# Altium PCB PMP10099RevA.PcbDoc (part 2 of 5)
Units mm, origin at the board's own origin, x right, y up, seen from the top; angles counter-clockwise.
Board outline 227.58 x 89.92 mm, 2 copper layers (Top Layer, Bottom Layer), stack 1.575 mm thick; 558 components, 261 nets, 1374 pads, 560 vias.
Unrouted connection lines stored in the file: 7.
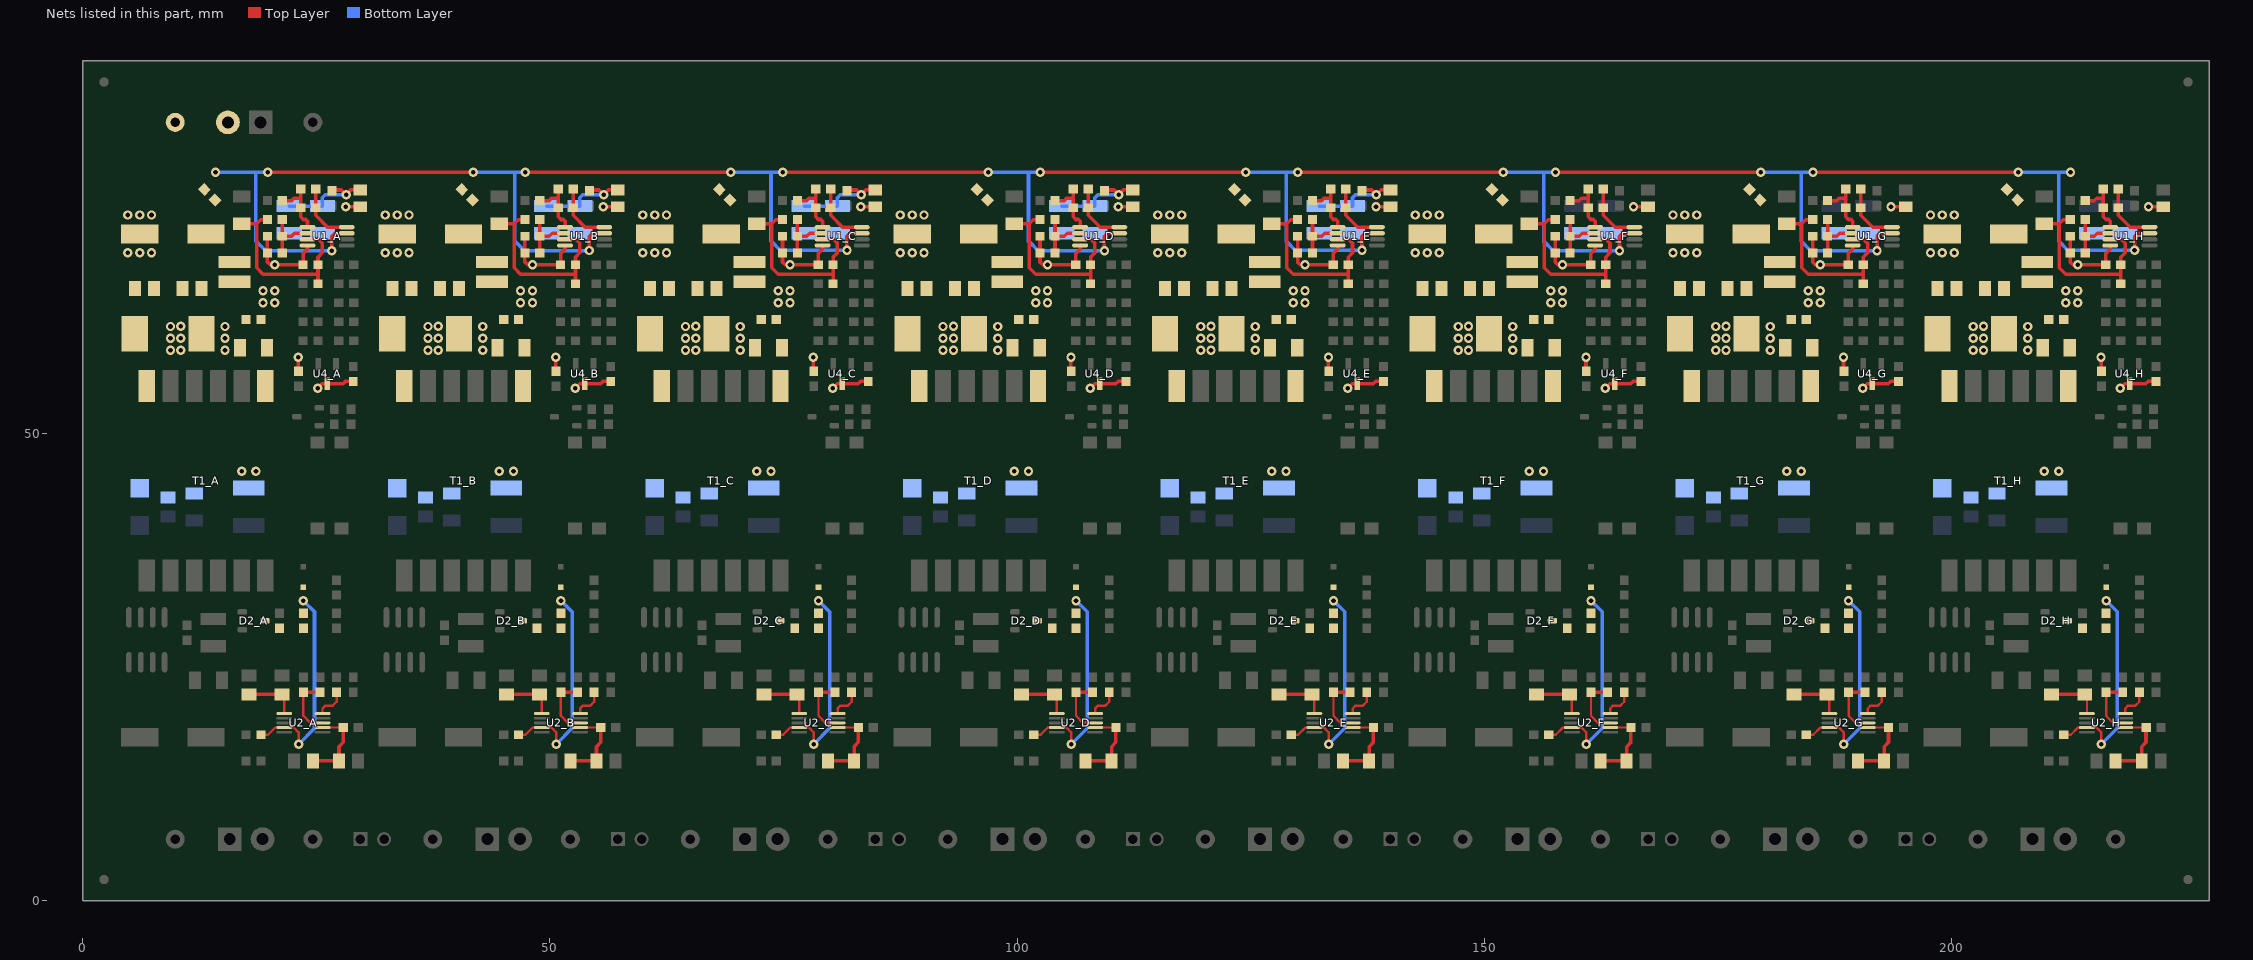
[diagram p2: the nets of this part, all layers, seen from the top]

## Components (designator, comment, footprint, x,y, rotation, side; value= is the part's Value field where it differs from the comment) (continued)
U1_H "UCC29002" DGK0008A_N 219.075,71.12 r0 top (schematic designator U1)
U2_A "LM5022" MUB10A_N 23.622,19.05 r0 top (schematic designator U2)
U2_B "LM5022" MUB10A_N 51.181,19.05 r0 top (schematic designator U2)
U2_C "LM5022" MUB10A_N 78.74,19.05 r0 top (schematic designator U2)
U2_D "LM5022" MUB10A_N 106.299,19.05 r0 top (schematic designator U2)
U2_E "LM5022" MUB10A_N 133.858,19.05 r0 top (schematic designator U2)
U2_F "LM5022" MUB10A_N 161.417,19.05 r0 top (schematic designator U2)
U2_G "LM5022" MUB10A_N 188.976,19.05 r0 top (schematic designator U2)
U2_H "LM5022" MUB10A_N 216.535,19.05 r0 top (schematic designator U2)
U3_A "FOD817A" N04C 26.416,44.45 r270 top (schematic designator U3)
U3_B "FOD817A" N04C 53.975,44.45 r270 top (schematic designator U3)
U3_C "FOD817A" N04C 81.534,44.45 r270 top (schematic designator U3)
U3_D "FOD817A" N04C 109.093,44.45 r270 top (schematic designator U3)
U3_E "FOD817A" N04C 136.652,44.45 r270 top (schematic designator U3)
U3_F "FOD817A" N04C 164.211,44.45 r270 top (schematic designator U3)
U3_G "FOD817A" N04C 191.77,44.45 r270 top (schematic designator U3)
U3_H "FOD817A" N04C 219.329,44.45 r270 top (schematic designator U3)
U4_A "LMV431" MF03A_N 26.162,56.388 r270 top (schematic designator U4)
U4_B "LMV431" MF03A_N 53.721,56.388 r270 top (schematic designator U4)
U4_C "LMV431" MF03A_N 81.28,56.388 r270 top (schematic designator U4)
U4_D "LMV431" MF03A_N 108.839,56.388 r270 top (schematic designator U4)
U4_E "LMV431" MF03A_N 136.398,56.388 r270 top (schematic designator U4)
U4_F "LMV431" MF03A_N 163.957,56.388 r270 top (schematic designator U4)
U4_G "LMV431" MF03A_N 191.516,56.388 r270 top (schematic designator U4)
U4_H "LMV431" MF03A_N 219.075,56.388 r270 top (schematic designator U4)

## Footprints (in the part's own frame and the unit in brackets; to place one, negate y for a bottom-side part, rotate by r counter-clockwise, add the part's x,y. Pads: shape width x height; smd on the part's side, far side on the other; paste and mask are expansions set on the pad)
0603 [mm] "0603 from SM-752 data"
  rect 1x0.95 smd: 1(-0.8,0) 2(0.8,0)
  silkscreen extent -1.52,-0.69 1.52,0.69, body extent -0.87,-0.47 0.87,0.47, height 0.85
0805_140 [mm] "0805 / 1.4mm height"
  rect 1.15x1.45 smd: 1(-0.9,0) 2(0.9,0)
  silkscreen extent -0.1,-0.8 0.1,0.8, body extent -1.1,-0.72 1.1,0.72, height 1.4
0805_HV [mil] "0805 with 30mil clearance between pads"
  rect 50x63 smd: 1(-40,0) 2(40,0)
  silkscreen extent -74,-40 74,40, body extent -43,-29 43,29, height 43
1206 [mm] "1206 from SM-752 data"
  rect 1.3x1.85 smd: 1(-1.45,0) 2(1.45,0)
  silkscreen extent -2.4,-1.21 2.4,1.21, body extent -1.7,-0.9 1.7,0.9, height 1.35
1210 [mm] "1210 from SM-752 data"
  rect 1.3x2.7 smd: 1(-1.45,0) 2(1.45,0)
  silkscreen extent -2.32,-1.57 2.32,1.57, body extent -1.7,-1.35 1.7,1.35, height 1.35
1812 [mm]
  rect 1.6x3.4 smd: 1(-2,0) 2(2,0)
  silkscreen extent -0.8,-1.6 0.8,1.6, body extent -2.4,-1.7 2.4,1.7, height 1.35
CONN_PEC02SAAN [mm] "SULLINS"
  rect 1.5x1.5 hole 1.016: 1(-1.27,0)
  round 1.5 hole 1.016: 2(1.27,0)
  silkscreen extent -2.54,-1.27 2.54,1.27, body extent -2.54,-1.27 2.54,1.27, height 8.38
DGK0008A_N [mm] "TSOP, 8-Leads, Body 3x3mm, Pitch 0.65mm, IPC Medium Density"
  oval 1.7x0.45 smd mask+0.05: 1(-2.1,0.975) 2(-2.1,0.325) 3(-2.1,-0.325) 4(-2.1,-0.975) 5(2.1,-0.975) 6(2.1,-0.325) 7(2.1,0.325) 8(2.1,0.975)
  silkscreen extent -0.95,-1.55 0.95,1.55, body extent -2.45,-1.5 2.45,1.5, height 0.94
Fiducial10-30 [mm]
  round 1 smd mask+1: 1(0,0)
  Top Layer keep-out circle w1.678: c0,0 r0.75
Keystone5000 [mil] "For Keystone 500x miniature loop terminals"
  round 80 hole 40: 1(0,0)
  silkscreen extent -58,-58 58,58, body extent -49,-49 49,49, height 182
Keystone5001 [mil] "For Keystone 500x miniature loop terminals"
  round 80 hole 40: 1(0,0)
  silkscreen extent -58,-58 58,58, body extent -49,-49 49,49, height 182
MF03A_N [mm] "SOT23, 3-Leads, Body 2.9x1.3mm, Pitch 0.95mm, Lead Span 2.4mm, IPC Medium Density"
  rect 1.3x0.6 smd: 1(-1.05,0.95) 2(-1.05,-0.95) 3(1.05,0)
  silkscreen extent -1.17,-1.5 0.7,1.93, body extent -0.7,-1.5 0.7,1.5, height 1.12
MUB10A_N [mm] "TSSOP, 10-Leads, Body 3x3mm, Pitch 0.5mm, IPC Medium Density"
  oval 1.7x0.3 smd: 1(-2.05,1) 2(-2.05,0.5) 3(-2.05,0) 4(-2.05,-0.5) 5(-2.05,-1) 6(2.05,-1) 7(2.05,-0.5) 8(2.05,0) 9(2.05,0.5) 10(2.05,1)
  silkscreen extent -2.17,-1.6 0.8,1.82, body extent -1.6,-1.6 1.6,1.6, height 1.09
N04C [mm] "FAIRCHILD"
  rect 1.3x1.5 smd mask+0.065: 1(-4.587,1.27) 2(-4.612,-1.27) 3(4.588,-1.27) 4(4.613,1.27)
  silkscreen extent -3.56,-2.3 3.56,2.72, body extent -5.08,-2.3 5.08,2.3, height 3.87
SM_RADIAL_F [mm] "8 x 10.2mm:  Panasonic F"
  rect 4x2 smd: 1(-3.55,0) 2(3.55,0)
  silkscreen extent -4.25,-4.25 4.25,4.25, body extent -4.26,-4.26 4.26,4.26, height 10.5
SMA [mm] "Molded Diode, 2-Leads, Body 4.3x2.6mm, IPC Medium Density, based on OnSemi component dimensions and land pattern"
  rect 2x2 smd: 1(-2,0) 2(2,0)
  silkscreen extent -3.66,-1.57 2.79,1.57, body extent -2.6,-1.3 2.6,1.3, height 2.42
SMC [mil] "Molded Diode, 2-Leads, Body 6.9x5.8mm, IPC Medium Density, based on OnSemi component dimensions and land patterns"
  rect 110x150 smd: 1(-140.49,0) 2(140.49,0)
  silkscreen extent -221,-123 189,124, body extent -156,-116 156,116, height 91
sod-323 [mm] "NXP recommended land pattern"
  rect 0.6x0.6 smd paste-0.05: 1(-1.1,0) 2(1.1,0)
  silkscreen extent -2.06,-0.86 1.53,0.86, body extent -1.3,-0.67 1.3,0.68, height 1.1
SOIC-8 [mm] "duplicate of SO-8.  SOIC, 8-Leads, Body 5.0x4.0mm (max), Pitch 1.27mm, IPC Medium Density"
  oval 2.2x0.6 smd: 1(-2.4,1.905) 2(-2.4,0.635) 3(-2.4,-0.635) 4(-2.4,-1.905) 5(2.4,-1.905) 6(2.4,-0.635) 7(2.4,0.635) 8(2.4,1.905)
  silkscreen extent -0.9,-2.5 0.9,2.5, body extent -3,-2.45 3,2.45, height 1.63
SOT-23 [mm] "SOT23, 3-Leads, Body 2.9x1.3mm, Pitch 0.95mm, Lead Span 2.5mm, IPC Medium Density"
  rrect50% 1x0.6 smd: 1(-1.2,0.95) 2(-1.2,-0.95) 3(1.2,0)
  silkscreen extent -1.63,-1.5 0.7,1.5, body extent -1.16,-1.45 1.21,1.45, height 1
TERM_BLK_ED555-2DS [mil]
  rect 100x100 hole 50: 1(0,0)
  round 100 hole 50: 2(138,0)
  silkscreen extent -77,-159 215,113, body extent -69,-150 207,106, height 323
WE-MAPI_3020 [mm] "SMD, 2-Leads, Body 3.2x3.2mm"
  rect 1.3x3.4 smd: 1(-1.05,0) 2(1.05,0)
  silkscreen extent -0.1,-1.6 0.1,1.6, body extent -1.6,-1.6 1.6,1.6, height 2
WURTH_7491193912 [mm] "SMT, 12-Leads, Body 17.5x16mm, Pitch 2.54mm"
  rect 3.43x1.75 smd: 1(-10.155,6.35) 2(-10.155,3.81) 3(-10.155,1.27) 4(-10.155,-1.27) 5(-10.155,-3.81) 6(-10.155,-6.35) 7(10.155,-6.35) 8(10.155,-3.81) 9(10.155,-1.27) 10(10.155,1.27) 11(10.155,3.81) 12(10.155,6.35)
  silkscreen extent -8.5,-8.75 8,8.85, body extent -11.05,-8.75 11.05,8.75, height 8.3

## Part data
C1_A C1_B C1_C C1_D C1_E C1_F C1_G C1_H: "CAP, AL, 22 µF, 80 V, +/- 20%, 1.3 ohm, SMD"
C2_A C2_B C2_C C2_D C2_E C2_F C2_G C2_H: "CAP, CERM, 2.2 µF, 100 V, +/- 10%, X7R, 1210"
C3_A C3_B C3_C C3_D C3_E C3_F C3_G C3_H C8_A C8_B C8_C C8_D C8_E C8_F C8_G C8_H C9_A C9_B C9_C C9_D C9_E C9_F C9_G C9_H C14_A C14_B C14_C C14_D C14_E C14_F C14_G C14_H C16_A C16_B C16_C C16_D C16_E C16_F C16_G C16_H C24_A C24_B C24_C C24_D C24_E C24_F C24_G C24_H: "CAP, CERM, 0.1 µF, 50 V, +/- 10%, X7R, 0603"
C4_A C4_B C4_C C4_D C4_E C4_F C4_G C4_H C10_A C10_B C10_C C10_D C10_E C10_F C10_G C10_H: "CAP, CERM, 0.1 µF, 100 V, +/- 10%, X7R, 0805"
C5_A C5_B C5_C C5_D C5_E C5_F C5_G C5_H: "CAP, CERM, 33 pF, 100 V, +/- 5%, C0G/NP0, 0805"
C6_A C6_B C6_C C6_D C6_E C6_F C6_G C6_H: "CAP, AL, 330 µF, 16 V, +/- 20%, 0.16 ohm, SMD"
C7_A C7_B C7_C C7_D C7_E C7_F C7_G C7_H: "CAP, CERM, 10 µF, 25 V, +/- 10%, X7R, 1206"
C11_A C11_B C11_C C11_D C11_E C11_F C11_G C11_H C17_A C17_B C17_C C17_D C17_E C17_F C17_G C17_H C26_A C26_B C26_C C26_D C26_E C26_F C26_G C26_H: "CAP, CERM, 1 µF, 25 V, +/- 10%, X7R, 0603"
C12_A C12_B C12_C C12_D C12_E C12_F C12_G C12_H C13_A C13_B C13_C C13_D C13_E C13_F C13_G C13_H: "CAP, CERM, 56 pF, 50 V, +/- 5%, C0G/NP0, 0603"
C15_A C15_B C15_C C15_D C15_E C15_F C15_G C15_H C18_A C18_B C18_C C18_D C18_E C18_F C18_G C18_H: "CAP, CERM, 1000 pF, 50 V, +/- 10%, X7R, 0603"
C19_A C19_B C19_C C19_D C19_E C19_F C19_G C19_H C20_A C20_B C20_C C20_D C20_E C20_F C20_G C20_H: "CAP, CERM, 47 µF, 6.3 V, +/- 10%, X7R, 1210"
C21_A C21_B C21_C C21_D C21_E C21_F C21_G C21_H: "CAP, CERM, 10 µF, 10 V, +/- 10%, X7R, 0805_140"
C22_A C22_B C22_C C22_D C22_E C22_F C22_G C22_H: "CAP, CERM, 22 pF, 50 V, +/- 5%, C0G/NP0, 0603"
C23_A C23_B C23_C C23_D C23_E C23_F C23_G C23_H: "CAP, CERM, 4700 pF, 50 V, +/- 10%, X7R, 0603"
C25_A C25_B C25_C C25_D C25_E C25_F C25_G C25_H: "CAP, CERM, 1000 pF, 2000 V, +/- 10%, X7R, 1812"
D1_A D1_B D1_C D1_D D1_E D1_F D1_G D1_H: library part MURA120T3G, "Diode, Ultrafast, 200 V, 1 A, SMA"
D2_A D2_B D2_C D2_D D2_E D2_F D2_G D2_H D5_A D5_B D5_C D5_D D5_E D5_F D5_G D5_H: library part BAS16-7-F, "Diode, Ultrafast, 75 V, 0.3 A, SOT-23"
D3_A D3_B D3_C D3_D D3_E D3_F D3_G D3_H: library part MBRS340T3G, "Diode, Schottky, 60 V, 3 A, SMC"
D4_A D4_B D4_C D4_D D4_E D4_F D4_G D4_H: "Diode, Zener, 12 V, 300 mW, SOD-323"
FID1 FID2 FID3 FID4: "Fiducial mark.  There is nothing to buy or mount."
J1_A J1_B J1_C J1_D J1_E J1_F J1_G J1_H J9: "Terminal Block, 6A, 3.5mm Pitch, 2-Pos, TH"
J2 J3 J4 J5 J6 J7 J8: "Header, 100mil, 2x1, Tin, TH"
L1_A L1_B L1_C L1_D L1_E L1_F L1_G L1_H: library part 744383360033, "Inductor, 330 nH, 5.5 A, 0.014 ohm, SMD"
Q1_A Q1_B Q1_C Q1_D Q1_E Q1_F Q1_G Q1_H: "MOSFET, N-CH, 150 V, 4.1 A, SOIC-8"
R1_A R1_B R1_C R1_D R1_E R1_F R1_G R1_H: "RES, 47 k, 5%, 0.25 W, 1206"
R2_A R2_B R2_C R2_D R2_E R2_F R2_G R2_H: "RES, 100 ohm, 5%, 0.125W, 0805"
R3_A R3_B R3_C R3_D R3_E R3_F R3_G R3_H: "RES, 0.1, 5%, 0.25 W, 1206"
R4_A R4_B R4_C R4_D R4_E R4_F R4_G R4_H: "RES, 78.7k ohm, 1%, 0.125W, 0805"
R5_A R5_B R5_C R5_D R5_E R5_F R5_G R5_H: "RES, 10.0 ohm, 1%, 0.125W, 0805"
R6_A R6_B R6_C R6_D R6_E R6_F R6_G R6_H: "RES, 10.0, 1%, 0.1 W, 0603"
R7_A R7_B R7_C R7_D R7_E R7_F R7_G R7_H: "RES, 3.92k ohm, 1%, 0.125W, 0805"
R8_A R8_B R8_C R8_D R8_E R8_F R8_G R8_H R9_A R9_B R9_C R9_D R9_E R9_F R9_G R9_H: "RES, 499, 1%, 0.1 W, 0603"
R10_A R10_B R10_C R10_D R10_E R10_F R10_G R10_H R14_A R14_B R14_C R14_D R14_E R14_F R14_G R14_H: "RES, 45.3 k, 1%, 0.1 W, 0603"
R11_A R11_B R11_C R11_D R11_E R11_F R11_G R11_H: "RES, 200, 1%, 0.1 W, 0603"
R12_A R12_B R12_C R12_D R12_E R12_F R12_G R12_H R13_A R13_B R13_C R13_D R13_E R13_F R13_G R13_H R18_A R18_B R18_C R18_D R18_E R18_F R18_G R18_H: "RES, 0, 5%, 0.1 W, 0603"
R15_A R15_B R15_C R15_D R15_E R15_F R15_G R15_H: "RES, 100, 1%, 0.1 W, 0603"
R16_A R16_B R16_C R16_D R16_E R16_F R16_G R16_H: "RES, 154, 1%, 0.1 W, 0603"
R17_A R17_B R17_C R17_D R17_E R17_F R17_G R17_H: "RES, 3.32, 1%, 0.1 W, 0603"
R19_A R19_B R19_C R19_D R19_E R19_F R19_G R19_H: "RES, 48.7 k, 1%, 0.1 W, 0603"
R20_A R20_B R20_C R20_D R20_E R20_F R20_G R20_H: "RES, 0.27, 1%, 0.25 W, 1206"
R21_A R21_B R21_C R21_D R21_E R21_F R21_G R21_H R23_A R23_B R23_C R23_D R23_E R23_F R23_G R23_H: "RES, 2.49 k, 1%, 0.1 W, 0603"
R22_A R22_B R22_C R22_D R22_E R22_F R22_G R22_H: "RES, 10.0 k, 1%, 0.1 W, 0603"
R24_A R24_B R24_C R24_D R24_E R24_F R24_G R24_H R25_A R25_B R25_C R25_D R25_E R25_F R25_G R25_H: "RES, 100 k, 1%, 0.1 W, 0603"
R26_A R26_B R26_C R26_D R26_E R26_F R26_G R26_H: "RES, 1.00 k, 1%, 0.1 W, 0603"
R27_A R27_B R27_C R27_D R27_E R27_F R27_G R27_H: "RES, 11.5 k, 1%, 0.1 W, 0603"
T1_A T1_B T1_C T1_D T1_E T1_F T1_G T1_H: "Transformer, 120 uH, SMT"
TP1_A TP1_B TP1_C TP1_D TP1_E TP1_F TP1_G TP1_H TP3: "Test Point, Miniature, Red, TH"
TP2_A TP2_B TP2_C TP2_D TP2_E TP2_F TP2_G TP2_H TP4: "Test Point, Miniature, Black, TH"
U1_A U1_B U1_C U1_D U1_E U1_F U1_G U1_H: library part UCC29002DGK, "ADVANCED 8-PIN LOAD SHARE CONTROLLER, DGK0008A"
U2_A U2_B U2_C U2_D U2_E U2_F U2_G U2_H: library part LM5022MM, "60V Low Side Controller for Boost and SEPIC, 10-pin MSOP"
U3_A U3_B U3_C U3_D U3_E U3_F U3_G U3_H: library part FOD817DS, "Optocoupler, 5kV RMS, SMT"
U4_A U4_B U4_C U4_D U4_E U4_F U4_G U4_H: library part LMV431AIMF, "Low-Voltage (1.24V) Adjustable Precision Shunt Regulator, 3-pin SOT-23"

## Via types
v1: diameter 1, hole 0.5, Top Layer to Bottom Layer, 560 vias

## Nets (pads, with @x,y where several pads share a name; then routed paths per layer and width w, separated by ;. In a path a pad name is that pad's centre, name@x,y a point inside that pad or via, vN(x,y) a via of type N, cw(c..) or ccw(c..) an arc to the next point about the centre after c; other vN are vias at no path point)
GND: C6_A.2 C6_B.2 C6_C.2 C6_D.2 C6_E.2 C6_F.2 C6_G.2 C6_H.2 C7_A.2 C7_B.2 C7_C.2 C7_D.2 C7_E.2 C7_F.2 C7_G.2 C7_H.2 C8_A.2 C8_B.2 C8_C.2 C8_D.2 C8_E.2 C8_F.2 C8_G.2 C8_H.2 C9_A.2 C9_B.2 C9_C.2 C9_D.2 C9_E.2 C9_F.2 C9_G.2 C9_H.2 C13_A.2 C13_B.2 C13_C.2 C13_D.2 C13_E.2 C13_F.2 C13_G.2 C13_H.2 C14_A.2 C14_B.2 C14_C.2 C14_D.2 C14_E.2 C14_F.2 C14_G.2 C14_H.2 C19_A.2 C19_B.2 C19_C.2 C19_D.2 C19_E.2 C19_F.2 C19_G.2 C19_H.2 C20_A.2 C20_B.2 C20_C.2 C20_D.2 C20_E.2 C20_F.2 C20_G.2 C20_H.2 C21_A.2 C21_B.2 C21_C.2 C21_D.2 C21_E.2 C21_F.2 C21_G.2 C21_H.2 C25_A.1 C25_B.1 C25_C.1 C25_D.1 C25_E.1 C25_F.1 C25_G.1 C25_H.1 C26_A.2 C26_B.2 C26_C.2 C26_D.2 C26_E.2 C26_F.2 C26_G.2 C26_H.2 J9.2 R14_A.1 R14_B.1 R14_C.1 R14_D.1 R14_E.1 R14_F.1 R14_G.1 R14_H.1 R27_A.1 R27_B.1 R27_C.1 R27_D.1 R27_E.1 R27_F.1 R27_G.1 R27_H.1 T1_A.7 T1_B.7 T1_C.7 T1_D.7 T1_E.7 T1_F.7 T1_G.7 T1_H.7 TP4.1 U1_A.4 U1_B.4 U1_C.4 U1_D.4 U1_E.4 U1_F.4 U1_G.4 U1_H.4 U4_A.3 U4_B.3 U4_C.3 U4_D.3 U4_E.3 U4_F.3 U4_G.3 U4_H.3 | length 129
  Top Layer w0.381: C13_A.2@19.774,71.12 R14_A.1@19.774,69.342 19.774,68.364 20.066,68.072 v1(20.574,68.072) C14_A.2@23.584,68.072 23.584,69.282 24.062,69.76 U1_A.4@24.062,70.145 ; v1(23.081,58.166) 23.081,56.713 C26_A.2@23.114,56.68 ; v1(25.146,54.864) 25.62,55.338 U4_A.3@26.162,55.338 27.878,55.338 28.128,55.588 R27_A.1@28.956,55.588 ; v1(28.161,74.295) 29.707,74.295 C21_A.2@29.718,74.284 ; C13_B.2@47.333,71.12 R14_B.1@47.333,69.342 47.333,68.364 47.625,68.072 v1(48.133,68.072) C14_B.2@51.143,68.072 51.143,69.282 51.621,69.76 U1_B.4@51.621,70.145 ; v1(50.64,58.166) 50.64,56.713 C26_B.2@50.673,56.68 ; v1(52.705,54.864) 53.179,55.338 U4_B.3@53.721,55.338 55.437,55.338 55.687,55.588 R27_B.1@56.515,55.588 ; v1(55.72,74.295) 57.266,74.295 C21_B.2@57.277,74.284 ; C13_C.2@74.892,71.12 R14_C.1@74.892,69.342 74.892,68.364 75.184,68.072 v1(75.692,68.072) C14_C.2@78.702,68.072 78.702,69.282 79.18,69.76 U1_C.4@79.18,70.145 ; v1(78.199,58.166) 78.199,56.713 C26_C.2@78.232,56.68 ; v1(80.264,54.864) 80.738,55.338 U4_C.3@81.28,55.338 82.996,55.338 83.246,55.588 R27_C.1@84.074,55.588 ; v1(83.279,74.295) 84.825,74.295 C21_C.2@84.836,74.284 ; C13_D.2@102.451,71.12 R14_D.1@102.451,69.342 102.451,68.364 102.743,68.072 v1(103.251,68.072) C14_D.2@106.261,68.072 106.261,69.282 106.739,69.76 U1_D.4@106.739,70.145 ; v1(105.758,58.166) 105.758,56.713 C26_D.2@105.791,56.68 ; v1(107.823,54.864) 108.297,55.338 U4_D.3@108.839,55.338 110.555,55.338 110.805,55.588 R27_D.1@111.633,55.588 ; v1(110.838,74.295) 112.384,74.295 C21_D.2@112.395,74.284 ; C13_E.2@130.01,71.12 R14_E.1@130.01,69.342 130.01,68.364 130.302,68.072 v1(130.81,68.072) C14_E.2@133.82,68.072 133.82,69.282 134.298,69.76 U1_E.4@134.298,70.145 ; v1(133.317,58.166) 133.317,56.713 C26_E.2@133.35,56.68 ; v1(135.382,54.864) 135.856,55.338 U4_E.3@136.398,55.338 138.114,55.338 138.364,55.588 R27_E.1@139.192,55.588 ; v1(138.397,74.295) 139.943,74.295 C21_E.2@139.954,74.284 ; C13_F.2@157.569,71.12 R14_F.1@157.569,69.342 157.569,68.364 157.861,68.072 v1(158.369,68.072) C14_F.2@161.379,68.072 161.379,69.282 161.857,69.76 U1_F.4@161.857,70.145 ; v1(160.876,58.166) 160.876,56.713 C26_F.2@160.909,56.68 ; v1(162.941,54.864) 163.415,55.338 U4_F.3@163.957,55.338 165.673,55.338 165.923,55.588 R27_F.1@166.751,55.588 ; v1(165.956,74.295) 167.502,74.295 C21_F.2@167.513,74.284 ; C13_G.2@185.128,71.12 R14_G.1@185.128,69.342 185.128,68.364 185.42,68.072 v1(185.928,68.072) C14_G.2@188.938,68.072 188.938,69.282 189.416,69.76 U1_G.4@189.416,70.145 ; v1(188.435,58.166) 188.435,56.713 C26_G.2@188.468,56.68 ; v1(190.5,54.864) 190.974,55.338 U4_G.3@191.516,55.338 193.232,55.338 193.482,55.588 R27_G.1@194.31,55.588 ; v1(193.515,74.295) 195.061,74.295 C21_G.2@195.072,74.284 ; C13_H.2@212.687,71.12 R14_H.1@212.687,69.342 212.687,68.364 212.979,68.072 v1(213.487,68.072) C14_H.2@216.497,68.072 216.497,69.282 216.975,69.76 U1_H.4@216.975,70.145 ; v1(215.994,58.166) 215.994,56.713 C26_H.2@216.027,56.68 ; v1(218.059,54.864) 218.533,55.338 U4_H.3@219.075,55.338 220.791,55.338 221.041,55.588 R27_H.1@221.869,55.588 ; v1(221.074,74.295) 222.62,74.295 C21_H.2@222.631,74.284
  other v1: 17.018,45.974 18.542,45.974 44.577,45.974 46.101,45.974 72.136,45.974 73.66,45.974 99.695,45.974 101.219,45.974 127.254,45.974 128.778,45.974 154.813,45.974 156.337,45.974 182.372,45.974 183.896,45.974 209.931,45.974 211.455,45.974 19.304,64.008 20.574,64.008 46.863,64.008 48.133,64.008 74.422,64.008 75.692,64.008 101.981,64.008 103.251,64.008 129.54,64.008 130.81,64.008 157.099,64.008 158.369,64.008 184.658,64.008 185.928,64.008 212.217,64.008 213.487,64.008 19.304,65.278 20.574,65.278 46.863,65.278 48.133,65.278 74.422,65.278 75.692,65.278 101.981,65.278 103.251,65.278 129.54,65.278 130.81,65.278 157.099,65.278 158.369,65.278 184.658,65.278 185.928,65.278 212.217,65.278 213.487,65.278 4.826,69.342 6.096,69.342 7.366,69.342 32.385,69.342 33.655,69.342 34.925,69.342 59.944,69.342 61.214,69.342 62.484,69.342 87.503,69.342 88.773,69.342 90.043,69.342 115.062,69.342 116.332,69.342 117.602,69.342 142.621,69.342 143.891,69.342 145.161,69.342 170.18,69.342 171.45,69.342 172.72,69.342 197.739,69.342 199.009,69.342 200.279,69.342 4.826,73.406 6.096,73.406 7.366,73.406 32.385,73.406 33.655,73.406 34.925,73.406 59.944,73.406 61.214,73.406 62.484,73.406 87.503,73.406 88.773,73.406 90.043,73.406 115.062,73.406 116.332,73.406 117.602,73.406 142.621,73.406 143.891,73.406 145.161,73.406 170.18,73.406 171.45,73.406 172.72,73.406 197.739,73.406 199.009,73.406 200.279,73.406
LS: U1_A.7 U1_B.7 U1_C.7 U1_D.7 U1_E.7 U1_F.7 U1_G.7 U1_H.7 | length 351.8
  Top Layer w0.381: v1(19.812,77.978) v1(41.783,77.978) ; v1(26.67,69.57) 26.662,69.578 26.662,71.12 26.987,71.445 U1_A.7@28.262,71.445 ; v1(47.371,77.978) v1(69.342,77.978) ; v1(54.229,69.596) 54.229,71.128 54.546,71.445 U1_B.7@55.821,71.445 ; v1(74.93,77.978) v1(96.901,77.978) ; v1(81.788,69.619) 81.788,71.128 82.105,71.445 U1_C.7@83.38,71.445 ; v1(102.489,77.978) v1(124.46,77.978) ; v1(109.347,69.57) 109.347,71.128 109.664,71.445 U1_D.7@110.939,71.445 ; v1(130.048,77.978) v1(152.019,77.978) ; v1(136.906,69.619) 136.906,71.128 137.223,71.445 U1_E.7@138.498,71.445 ; v1(157.607,77.978) v1(179.578,77.978) ; v1(164.465,69.57) 164.465,71.128 164.782,71.445 U1_F.7@166.057,71.445 ; v1(185.166,77.978) v1(207.137,77.978) ; v1(192.024,69.57) 192.024,71.128 192.341,71.445 U1_G.7@193.616,71.445 ; v1(219.583,69.619) 219.583,71.128 219.9,71.445 U1_H.7@221.175,71.445
  Bottom Layer w0.381: v1(14.224,77.978) 18.542,77.978 ; v1(19.812,77.978) 18.542,77.978 ; v1(26.67,69.57) 19.584,69.57 18.542,70.612 18.542,77.978 ; v1(41.783,77.978) 46.228,77.978 ; v1(47.371,77.978) 46.228,77.978 ; v1(54.229,69.596) 47.244,69.596 46.228,70.612 46.228,77.978 ; v1(69.342,77.978) 73.66,77.978 ; v1(74.93,77.978) 73.66,77.978 ; v1(81.788,69.619) 74.653,69.619 73.66,70.612 73.66,77.978 ; v1(96.901,77.978) 101.219,77.978 ; v1(102.489,77.978) 101.219,77.978 ; v1(109.347,69.57) 102.261,69.57 101.219,70.612 101.219,77.978 ; v1(124.46,77.978) 128.778,77.978 ; v1(130.048,77.978) 128.778,77.978 ; v1(136.906,69.619) 129.771,69.619 128.778,70.612 128.778,77.978 ; v1(152.019,77.978) 156.337,77.978 ; v1(157.607,77.978) 156.337,77.978 ; v1(164.465,69.57) 157.379,69.57 156.337,70.612 156.337,77.978 ; v1(179.578,77.978) 183.896,77.978 ; v1(185.166,77.978) 183.896,77.978 ; v1(192.024,69.57) 184.938,69.57 183.896,70.612 183.896,77.978 ; v1(207.137,77.978) 211.455,77.978 ; v1(212.725,77.978) 211.455,77.978 ; v1(219.583,69.619) 212.448,69.619 211.455,70.612 211.455,77.978
NetC4_A_2: C4_A.2 D1_A.1 R1_A.1
NetC4_B_2: C4_B.2 D1_B.1 R1_B.1
NetC4_C_2: C4_C.2 D1_C.1 R1_C.1
NetC4_D_2: C4_D.2 D1_D.1 R1_D.1
NetC4_E_2: C4_E.2 D1_E.1 R1_E.1
NetC4_F_2: C4_F.2 D1_F.1 R1_F.1
NetC4_G_2: C4_G.2 D1_G.1 R1_G.1
NetC4_H_2: C4_H.2 D1_H.1 R1_H.1
NetC5_A_1: C5_A.1 R2_A.1
NetC5_A_2: C5_A.2 D3_A.2 T1_A.12
NetC5_B_1: C5_B.1 R2_B.1
NetC5_B_2: C5_B.2 D3_B.2 T1_B.12
NetC5_C_1: C5_C.1 R2_C.1
NetC5_C_2: C5_C.2 D3_C.2 T1_C.12
NetC5_D_1: C5_D.1 R2_D.1
NetC5_D_2: C5_D.2 D3_D.2 T1_D.12
NetC5_E_1: C5_E.1 R2_E.1
NetC5_E_2: C5_E.2 D3_E.2 T1_E.12
NetC5_F_1: C5_F.1 R2_F.1
NetC5_F_2: C5_F.2 D3_F.2 T1_F.12
NetC5_G_1: C5_G.1 R2_G.1
NetC5_G_2: C5_G.2 D3_G.2 T1_G.12
NetC5_H_1: C5_H.1 R2_H.1
NetC5_H_2: C5_H.2 D3_H.2 T1_H.12
NetC6_A_1: C6_A.1 C9_A.1 C14_A.1 L1_A.2 R3_A.1 R8_A.2 R12_A.2 U1_A.3 | length 20.8
  Top Layer w0.381: R3_A.1@17.018,72.464 18.616,72.464 ; R8_A.2@19.774,72.898 19.05,72.898 18.616,72.464 ; U1_A.3@24.062,70.795 25.217,70.795 25.654,70.358 25.654,69.342 25.184,68.872 C14_A.1@25.184,68.072 25.184,67.056 ; R12_A.2@25.184,66.04 25.184,67.056 ; 18.616,72.464 18.616,67.744 19.304,67.056 25.184,67.056
NetC6_B_1: C6_B.1 C9_B.1 C14_B.1 L1_B.2 R3_B.1 R8_B.2 R12_B.2 U1_B.3 | length 20.8
  Top Layer w0.381: R3_B.1@44.577,72.464 46.175,72.464 ; R8_B.2@47.333,72.898 46.609,72.898 46.175,72.464 ; U1_B.3@51.621,70.795 52.776,70.795 53.213,70.358 53.213,69.342 52.743,68.872 C14_B.1@52.743,68.072 52.743,67.056 ; R12_B.2@52.743,66.04 52.743,67.056 ; 46.175,72.464 46.175,67.744 46.863,67.056 52.743,67.056
NetC6_C_1: C6_C.1 C9_C.1 C14_C.1 L1_C.2 R3_C.1 R8_C.2 R12_C.2 U1_C.3 | length 20.8
  Top Layer w0.381: R3_C.1@72.136,72.464 73.734,72.464 ; R8_C.2@74.892,72.898 74.168,72.898 73.734,72.464 ; U1_C.3@79.18,70.795 80.335,70.795 80.772,70.358 80.772,69.342 80.302,68.872 C14_C.1@80.302,68.072 80.302,67.056 ; R12_C.2@80.302,66.04 80.302,67.056 ; 73.734,72.464 73.734,67.744 74.422,67.056 80.302,67.056
NetC6_D_1: C6_D.1 C9_D.1 C14_D.1 L1_D.2 R3_D.1 R8_D.2 R12_D.2 U1_D.3 | length 20.8
  Top Layer w0.381: R3_D.1@99.695,72.464 101.293,72.464 ; R8_D.2@102.451,72.898 101.727,72.898 101.293,72.464 ; U1_D.3@106.739,70.795 107.894,70.795 108.331,70.358 108.331,69.342 107.861,68.872 C14_D.1@107.861,68.072 107.861,67.056 ; R12_D.2@107.861,66.04 107.861,67.056 ; 101.293,72.464 101.293,67.744 101.981,67.056 107.861,67.056
NetC6_E_1: C6_E.1 C9_E.1 C14_E.1 L1_E.2 R3_E.1 R8_E.2 R12_E.2 U1_E.3 | length 20.8
  Top Layer w0.381: R3_E.1@127.254,72.464 128.852,72.464 ; R8_E.2@130.01,72.898 129.286,72.898 128.852,72.464 ; U1_E.3@134.298,70.795 135.453,70.795 135.89,70.358 135.89,69.342 135.42,68.872 C14_E.1@135.42,68.072 135.42,67.056 ; R12_E.2@135.42,66.04 135.42,67.056 ; 128.852,72.464 128.852,67.744 129.54,67.056 135.42,67.056
NetC6_F_1: C6_F.1 C9_F.1 C14_F.1 L1_F.2 R3_F.1 R8_F.2 R12_F.2 U1_F.3 | length 20.8
  Top Layer w0.381: R3_F.1@154.813,72.464 156.411,72.464 ; R8_F.2@157.569,72.898 156.845,72.898 156.411,72.464 ; U1_F.3@161.857,70.795 163.012,70.795 163.449,70.358 163.449,69.342 162.979,68.872 C14_F.1@162.979,68.072 162.979,67.056 ; R12_F.2@162.979,66.04 162.979,67.056 ; 156.411,72.464 156.411,67.744 157.099,67.056 162.979,67.056
NetC6_G_1: C6_G.1 C9_G.1 C14_G.1 L1_G.2 R3_G.1 R8_G.2 R12_G.2 U1_G.3 | length 20.8
  Top Layer w0.381: R3_G.1@182.372,72.464 183.97,72.464 ; R8_G.2@185.128,72.898 184.404,72.898 183.97,72.464 ; U1_G.3@189.416,70.795 190.571,70.795 191.008,70.358 191.008,69.342 190.538,68.872 C14_G.1@190.538,68.072 190.538,67.056 ; R12_G.2@190.538,66.04 190.538,67.056 ; 183.97,72.464 183.97,67.744 184.658,67.056 190.538,67.056
NetC6_H_1: C6_H.1 C9_H.1 C14_H.1 L1_H.2 R3_H.1 R8_H.2 R12_H.2 U1_H.3 | length 20.8
  Top Layer w0.381: R3_H.1@209.931,72.464 211.529,72.464 ; R8_H.2@212.687,72.898 211.963,72.898 211.529,72.464 ; U1_H.3@216.975,70.795 218.13,70.795 218.567,70.358 218.567,69.342 218.097,68.872 C14_H.1@218.097,68.072 218.097,67.056 ; R12_H.2@218.097,66.04 218.097,67.056 ; 211.529,72.464 211.529,67.744 212.217,67.056 218.097,67.056
NetC7_A_1: C7_A.1 C8_A.1 D3_A.1 L1_A.1 R2_A.2
  other v1: 9.398,58.928 10.508,58.928 15.24,58.928 9.398,60.198 10.508,60.198 15.24,60.198 9.398,61.468 10.508,61.476 15.24,61.468
NetC7_B_1: C7_B.1 C8_B.1 D3_B.1 L1_B.1 R2_B.2
  other v1: 36.957,58.928 38.067,58.928 42.799,58.928 36.957,60.198 38.067,60.198 42.799,60.198 36.957,61.468 38.067,61.476 42.799,61.468
NetC7_C_1: C7_C.1 C8_C.1 D3_C.1 L1_C.1 R2_C.2
  other v1: 64.516,58.928 65.626,58.928 70.358,58.928 64.516,60.198 65.626,60.198 70.358,60.198 64.516,61.468 65.626,61.476 70.358,61.468
NetC7_D_1: C7_D.1 C8_D.1 D3_D.1 L1_D.1 R2_D.2
  other v1: 92.075,58.928 93.185,58.928 97.917,58.928 92.075,60.198 93.185,60.198 97.917,60.198 92.075,61.468 93.185,61.476 97.917,61.468
NetC7_E_1: C7_E.1 C8_E.1 D3_E.1 L1_E.1 R2_E.2
  other v1: 119.634,58.928 120.744,58.928 125.476,58.928 119.634,60.198 120.744,60.198 125.476,60.198 119.634,61.468 120.744,61.476 125.476,61.468
NetC7_F_1: C7_F.1 C8_F.1 D3_F.1 L1_F.1 R2_F.2
  other v1: 147.193,58.928 148.303,58.928 153.035,58.928 147.193,60.198 148.303,60.198 153.035,60.198 147.193,61.468 148.303,61.476 153.035,61.468
NetC7_G_1: C7_G.1 C8_G.1 D3_G.1 L1_G.1 R2_G.2
  other v1: 174.752,58.928 175.862,58.928 180.594,58.928 174.752,60.198 175.862,60.198 180.594,60.198 174.752,61.468 175.862,61.476 180.594,61.468
NetC7_H_1: C7_H.1 C8_H.1 D3_H.1 L1_H.1 R2_H.2
  other v1: 202.311,58.928 203.421,58.928 208.153,58.928 202.311,60.198 203.421,60.198 208.153,60.198 202.311,61.468 203.421,61.476 208.153,61.468
NetC10_A_1: C10_A.1 R5_A.1 U2_A.1 | length 5.7
  Top Layer w0.254: C10_A.1@21.336,22.098 21.572,21.862 U2_A.1@21.572,20.05
  Top Layer w0.381: R5_A.1@17.78,22.098 C10_A.1@21.336,22.098
NetC10_B_1: C10_B.1 R5_B.1 U2_B.1 | length 5.7
  Top Layer w0.254: C10_B.1@48.895,22.098 49.131,21.862 U2_B.1@49.131,20.05
  Top Layer w0.381: R5_B.1@45.339,22.098 C10_B.1@48.895,22.098
NetC10_C_1: C10_C.1 R5_C.1 U2_C.1 | length 5.7
  Top Layer w0.254: C10_C.1@76.454,22.098 76.69,21.862 U2_C.1@76.69,20.05
  Top Layer w0.381: R5_C.1@72.898,22.098 C10_C.1@76.454,22.098
NetC10_D_1: C10_D.1 R5_D.1 U2_D.1 | length 5.7
  Top Layer w0.254: C10_D.1@104.013,22.098 104.249,21.862 U2_D.1@104.249,20.05
  Top Layer w0.381: R5_D.1@100.457,22.098 C10_D.1@104.013,22.098
NetC10_E_1: C10_E.1 R5_E.1 U2_E.1 | length 5.7
  Top Layer w0.254: C10_E.1@131.572,22.098 131.808,21.862 U2_E.1@131.808,20.05
  Top Layer w0.381: R5_E.1@128.016,22.098 C10_E.1@131.572,22.098
NetC10_F_1: C10_F.1 R5_F.1 U2_F.1 | length 5.7
  Top Layer w0.254: C10_F.1@159.131,22.098 159.367,21.862 U2_F.1@159.367,20.05
  Top Layer w0.381: R5_F.1@155.575,22.098 C10_F.1@159.131,22.098
NetC10_G_1: C10_G.1 R5_G.1 U2_G.1 | length 5.7
  Top Layer w0.254: C10_G.1@186.69,22.098 186.926,21.862 U2_G.1@186.926,20.05
  Top Layer w0.381: R5_G.1@183.134,22.098 C10_G.1@186.69,22.098
NetC10_H_1: C10_H.1 R5_H.1 U2_H.1 | length 5.7
  Top Layer w0.254: C10_H.1@214.249,22.098 214.485,21.862 U2_H.1@214.485,20.05
  Top Layer w0.381: R5_H.1@210.693,22.098 C10_H.1@214.249,22.098
NetC11_A_1: C11_A.1 D2_A.3 R6_A.2
NetC11_B_1: C11_B.1 D2_B.3 R6_B.2
NetC11_C_1: C11_C.1 D2_C.3 R6_C.2
NetC11_D_1: C11_D.1 D2_D.3 R6_D.2
NetC11_E_1: C11_E.1 D2_E.3 R6_E.2
NetC11_F_1: C11_F.1 D2_F.3 R6_F.2
NetC11_G_1: C11_G.1 D2_G.3 R6_G.2
NetC11_H_1: C11_H.1 D2_H.3 R6_H.2
NetC12_A_1: C12_A.1 R10_A.2 U1_A.8 | length 6.7
  Top Layer w0.381: R10_A.2@24.93,76.2 C12_A.1@24.93,74.168 24.93,73.368 26.203,72.095 U1_A.8@28.262,72.095
NetC12_A_2: C12_A.2 R9_A.1 R10_A.1 U1_A.1 | length 6.6
  Top Layer w0.381: R9_A.1@21.374,74.93 22.352,74.93 22.606,75.184 23.33,75.184 ; R10_A.1@23.33,76.2 23.33,75.184 ; U1_A.1@24.062,72.095 24.062,72.734 23.876,72.92 23.622,72.92 23.33,73.212 C12_A.2@23.33,74.168 23.33,75.184
NetC12_B_1: C12_B.1 R10_B.2 U1_B.8 | length 6.7
  Top Layer w0.381: R10_B.2@52.489,76.2 C12_B.1@52.489,74.168 52.489,73.368 53.762,72.095 U1_B.8@55.821,72.095
NetC12_B_2: C12_B.2 R9_B.1 R10_B.1 U1_B.1 | length 6.6
  Top Layer w0.381: R9_B.1@48.933,74.93 49.911,74.93 50.165,75.184 50.889,75.184 ; R10_B.1@50.889,76.2 50.889,75.184 ; U1_B.1@51.621,72.095 51.621,72.734 51.435,72.92 51.181,72.92 50.889,73.212 C12_B.2@50.889,74.168 50.889,75.184
NetC12_C_1: C12_C.1 R10_C.2 U1_C.8 | length 6.7
  Top Layer w0.381: R10_C.2@80.048,76.2 C12_C.1@80.048,74.168 80.048,73.368 81.321,72.095 U1_C.8@83.38,72.095
NetC12_C_2: C12_C.2 R9_C.1 R10_C.1 U1_C.1 | length 6.6
  Top Layer w0.381: R9_C.1@76.492,74.93 77.47,74.93 77.724,75.184 78.448,75.184 ; R10_C.1@78.448,76.2 78.448,75.184 ; U1_C.1@79.18,72.095 79.18,72.734 78.994,72.92 78.74,72.92 78.448,73.212 C12_C.2@78.448,74.168 78.448,75.184
NetC12_D_1: C12_D.1 R10_D.2 U1_D.8 | length 6.7
  Top Layer w0.381: R10_D.2@107.607,76.2 C12_D.1@107.607,74.168 107.607,73.368 108.88,72.095 U1_D.8@110.939,72.095
NetC12_D_2: C12_D.2 R9_D.1 R10_D.1 U1_D.1 | length 6.6
  Top Layer w0.381: R9_D.1@104.051,74.93 105.029,74.93 105.283,75.184 106.007,75.184 ; R10_D.1@106.007,76.2 106.007,75.184 ; U1_D.1@106.739,72.095 106.739,72.734 106.553,72.92 106.299,72.92 106.007,73.212 C12_D.2@106.007,74.168 106.007,75.184
NetC12_E_1: C12_E.1 R10_E.2 U1_E.8 | length 6.7
  Top Layer w0.381: R10_E.2@135.166,76.2 C12_E.1@135.166,74.168 135.166,73.368 136.439,72.095 U1_E.8@138.498,72.095
NetC12_E_2: C12_E.2 R9_E.1 R10_E.1 U1_E.1 | length 6.6
  Top Layer w0.381: R9_E.1@131.61,74.93 132.588,74.93 132.842,75.184 133.566,75.184 ; R10_E.1@133.566,76.2 133.566,75.184 ; U1_E.1@134.298,72.095 134.298,72.734 134.112,72.92 133.858,72.92 133.566,73.212 C12_E.2@133.566,74.168 133.566,75.184
NetC12_F_1: C12_F.1 R10_F.2 U1_F.8 | length 6.7
  Top Layer w0.381: R10_F.2@162.725,76.2 C12_F.1@162.725,74.168 162.725,73.368 163.998,72.095 U1_F.8@166.057,72.095
NetC12_F_2: C12_F.2 R9_F.1 R10_F.1 U1_F.1 | length 6.6
  Top Layer w0.381: R9_F.1@159.169,74.93 160.147,74.93 160.401,75.184 161.125,75.184 ; R10_F.1@161.125,76.2 161.125,75.184 ; U1_F.1@161.857,72.095 161.857,72.734 161.671,72.92 161.417,72.92 161.125,73.212 C12_F.2@161.125,74.168 161.125,75.184
NetC12_G_1: C12_G.1 R10_G.2 U1_G.8 | length 6.7
  Top Layer w0.381: R10_G.2@190.284,76.2 C12_G.1@190.284,74.168 190.284,73.368 191.557,72.095 U1_G.8@193.616,72.095
NetC12_G_2: C12_G.2 R9_G.1 R10_G.1 U1_G.1 | length 6.6
  Top Layer w0.381: R9_G.1@186.728,74.93 187.706,74.93 187.96,75.184 188.684,75.184 ; R10_G.1@188.684,76.2 188.684,75.184 ; U1_G.1@189.416,72.095 189.416,72.734 189.23,72.92 188.976,72.92 188.684,73.212 C12_G.2@188.684,74.168 188.684,75.184
NetC12_H_1: C12_H.1 R10_H.2 U1_H.8 | length 6.7
  Top Layer w0.381: R10_H.2@217.843,76.2 C12_H.1@217.843,74.168 217.843,73.368 219.116,72.095 U1_H.8@221.175,72.095
NetC12_H_2: C12_H.2 R9_H.1 R10_H.1 U1_H.1 | length 6.6
  Top Layer w0.381: R9_H.1@214.287,74.93 215.265,74.93 215.519,75.184 216.243,75.184 ; R10_H.1@216.243,76.2 216.243,75.184 ; U1_H.1@216.975,72.095 216.975,72.734 216.789,72.92 216.535,72.92 216.243,73.212 C12_H.2@216.243,74.168 216.243,75.184
NetC13_A_1: C13_A.1 R8_A.1 R14_A.2 U1_A.2 | length 6.4
  Top Layer w0.381: R14_A.2@21.374,69.342 C13_A.1@21.374,71.12 ; R8_A.1@21.374,72.898 C13_A.1@21.374,71.12 ; U1_A.2@24.062,71.445 22.677,71.445 22.352,71.12 C13_A.1@21.374,71.12
NetC13_B_1: C13_B.1 R8_B.1 R14_B.2 U1_B.2 | length 6.4
  Top Layer w0.381: R14_B.2@48.933,69.342 C13_B.1@48.933,71.12 ; R8_B.1@48.933,72.898 C13_B.1@48.933,71.12 ; U1_B.2@51.621,71.445 50.236,71.445 49.911,71.12 C13_B.1@48.933,71.12
NetC13_C_1: C13_C.1 R8_C.1 R14_C.2 U1_C.2 | length 6.4
  Top Layer w0.381: R14_C.2@76.492,69.342 C13_C.1@76.492,71.12 ; R8_C.1@76.492,72.898 C13_C.1@76.492,71.12 ; U1_C.2@79.18,71.445 77.795,71.445 77.47,71.12 C13_C.1@76.492,71.12
NetC13_D_1: C13_D.1 R8_D.1 R14_D.2 U1_D.2 | length 6.4
  Top Layer w0.381: R14_D.2@104.051,69.342 C13_D.1@104.051,71.12 ; R8_D.1@104.051,72.898 C13_D.1@104.051,71.12 ; U1_D.2@106.739,71.445 105.354,71.445 105.029,71.12 C13_D.1@104.051,71.12
NetC13_E_1: C13_E.1 R8_E.1 R14_E.2 U1_E.2 | length 6.4
  Top Layer w0.381: R14_E.2@131.61,69.342 C13_E.1@131.61,71.12 ; R8_E.1@131.61,72.898 C13_E.1@131.61,71.12 ; U1_E.2@134.298,71.445 132.913,71.445 132.588,71.12 C13_E.1@131.61,71.12
NetC13_F_1: C13_F.1 R8_F.1 R14_F.2 U1_F.2 | length 6.4
  Top Layer w0.381: R14_F.2@159.169,69.342 C13_F.1@159.169,71.12 ; R8_F.1@159.169,72.898 C13_F.1@159.169,71.12 ; U1_F.2@161.857,71.445 160.472,71.445 160.147,71.12 C13_F.1@159.169,71.12
NetC13_G_1: C13_G.1 R8_G.1 R14_G.2 U1_G.2 | length 6.4
  Top Layer w0.381: R14_G.2@186.728,69.342 C13_G.1@186.728,71.12 ; R8_G.1@186.728,72.898 C13_G.1@186.728,71.12 ; U1_G.2@189.416,71.445 188.031,71.445 187.706,71.12 C13_G.1@186.728,71.12
NetC13_H_1: C13_H.1 R8_H.1 R14_H.2 U1_H.2 | length 6.4
  Top Layer w0.381: R14_H.2@214.287,69.342 C13_H.1@214.287,71.12 ; R8_H.1@214.287,72.898 C13_H.1@214.287,71.12 ; U1_H.2@216.975,71.445 215.59,71.445 215.265,71.12 C13_H.1@214.287,71.12
NetC15_A_1: C15_A.1 R4_A.1 R7_A.2 U2_A.7 | length 8.7
  Top Layer w0.254: U2_A.7@25.672,18.55 C15_A.1@27.894,18.55
  Top Layer w0.381: R4_A.1@24.676,14.986 R7_A.2@27.432,14.986 27.432,16.51 27.894,16.972 C15_A.1@27.894,18.55
NetC15_B_1: C15_B.1 R4_B.1 R7_B.2 U2_B.7 | length 8.7
  Top Layer w0.254: U2_B.7@53.231,18.55 C15_B.1@55.453,18.55
  Top Layer w0.381: R4_B.1@52.235,14.986 R7_B.2@54.991,14.986 54.991,16.51 55.453,16.972 C15_B.1@55.453,18.55
NetC15_C_1: C15_C.1 R4_C.1 R7_C.2 U2_C.7 | length 8.7
  Top Layer w0.254: U2_C.7@80.79,18.55 C15_C.1@83.012,18.55
  Top Layer w0.381: R4_C.1@79.794,14.986 R7_C.2@82.55,14.986 82.55,16.51 83.012,16.972 C15_C.1@83.012,18.55
NetC15_D_1: C15_D.1 R4_D.1 R7_D.2 U2_D.7 | length 8.7
  Top Layer w0.254: U2_D.7@108.349,18.55 C15_D.1@110.571,18.55
  Top Layer w0.381: R4_D.1@107.353,14.986 R7_D.2@110.109,14.986 110.109,16.51 110.571,16.972 C15_D.1@110.571,18.55
NetC15_E_1: C15_E.1 R4_E.1 R7_E.2 U2_E.7 | length 8.7
  Top Layer w0.254: U2_E.7@135.908,18.55 C15_E.1@138.13,18.55
  Top Layer w0.381: R4_E.1@134.912,14.986 R7_E.2@137.668,14.986 137.668,16.51 138.13,16.972 C15_E.1@138.13,18.55
NetC15_F_1: C15_F.1 R4_F.1 R7_F.2 U2_F.7 | length 8.7
  Top Layer w0.254: U2_F.7@163.467,18.55 C15_F.1@165.689,18.55
  Top Layer w0.381: R4_F.1@162.471,14.986 R7_F.2@165.227,14.986 165.227,16.51 165.689,16.972 C15_F.1@165.689,18.55
NetC15_G_1: C15_G.1 R4_G.1 R7_G.2 U2_G.7 | length 8.7
  Top Layer w0.254: U2_G.7@191.026,18.55 C15_G.1@193.248,18.55
  Top Layer w0.381: R4_G.1@190.03,14.986 R7_G.2@192.786,14.986 192.786,16.51 193.248,16.972 C15_G.1@193.248,18.55
NetC15_H_1: C15_H.1 R4_H.1 R7_H.2 U2_H.7 | length 8.7
  Top Layer w0.254: U2_H.7@218.585,18.55 C15_H.1@220.807,18.55
  Top Layer w0.381: R4_H.1@217.589,14.986 R7_H.2@220.345,14.986 220.345,16.51 220.807,16.972 C15_H.1@220.807,18.55
NetC16_A_1: C16_A.1 U2_A.10 | length 3.4
  Top Layer w0.254: U2_A.10@25.672,20.05 25.672,20.592 25.98,20.9 26.772,20.9 27.178,21.306 C16_A.1@27.178,22.314
NetC16_B_1: C16_B.1 U2_B.10 | length 3.4
  Top Layer w0.254: U2_B.10@53.231,20.05 53.231,20.592 53.539,20.9 54.331,20.9 54.737,21.306 C16_B.1@54.737,22.314
NetC16_C_1: C16_C.1 U2_C.10 | length 3.4
  Top Layer w0.254: U2_C.10@80.79,20.05 80.79,20.592 81.098,20.9 81.89,20.9 82.296,21.306 C16_C.1@82.296,22.314
NetC16_D_1: C16_D.1 U2_D.10 | length 3.4
  Top Layer w0.254: U2_D.10@108.349,20.05 108.349,20.592 108.657,20.9 109.449,20.9 109.855,21.306 C16_D.1@109.855,22.314
NetC16_E_1: C16_E.1 U2_E.10 | length 3.4
  Top Layer w0.254: U2_E.10@135.908,20.05 135.908,20.592 136.216,20.9 137.008,20.9 137.414,21.306 C16_E.1@137.414,22.314
NetC16_F_1: C16_F.1 U2_F.10 | length 3.4
  Top Layer w0.254: U2_F.10@163.467,20.05 163.467,20.592 163.775,20.9 164.567,20.9 164.973,21.306 C16_F.1@164.973,22.314
NetC16_G_1: C16_G.1 U2_G.10 | length 3.4
  Top Layer w0.254: U2_G.10@191.026,20.05 191.026,20.592 191.334,20.9 192.126,20.9 192.532,21.306 C16_G.1@192.532,22.314
NetC16_H_1: C16_H.1 U2_H.10 | length 3.4
  Top Layer w0.254: U2_H.10@218.585,20.05 218.585,20.592 218.893,20.9 219.685,20.9 220.091,21.306 C16_H.1@220.091,22.314
NetC17_A_1: C17_A.1 D4_A.1 R6_A.1 U2_A.4 | length 22.4
  Top Layer w0.254: C17_A.1@19.088,17.78 19.838,17.78 20.608,18.55 U2_A.4@21.572,18.55 22.598,18.55 23.114,18.034 v1(23.114,16.764)
  Bottom Layer w0.381: v1(23.114,16.764) 24.813,18.463 24.813,30.94 v1(23.622,32.131)
NetC17_B_1: C17_B.1 D4_B.1 R6_B.1 U2_B.4 | length 22.4
  Top Layer w0.254: C17_B.1@46.647,17.78 47.397,17.78 48.167,18.55 U2_B.4@49.131,18.55 50.157,18.55 50.673,18.034 v1(50.673,16.764)
  Bottom Layer w0.381: v1(50.673,16.764) 52.372,18.463 52.372,30.94 v1(51.181,32.131)
NetC17_C_1: C17_C.1 D4_C.1 R6_C.1 U2_C.4 | length 22.4
  Top Layer w0.254: C17_C.1@74.206,17.78 74.956,17.78 75.726,18.55 U2_C.4@76.69,18.55 77.716,18.55 78.232,18.034 v1(78.232,16.764)
  Bottom Layer w0.381: v1(78.232,16.764) 79.931,18.463 79.931,30.94 v1(78.74,32.131)
NetC17_D_1: C17_D.1 D4_D.1 R6_D.1 U2_D.4 | length 22.4
  Top Layer w0.254: C17_D.1@101.765,17.78 102.515,17.78 103.285,18.55 U2_D.4@104.249,18.55 105.275,18.55 105.791,18.034 v1(105.791,16.764)
  Bottom Layer w0.381: v1(105.791,16.764) 107.49,18.463 107.49,30.94 v1(106.299,32.131)
NetC17_E_1: C17_E.1 D4_E.1 R6_E.1 U2_E.4 | length 22.4
  Top Layer w0.254: C17_E.1@129.324,17.78 130.074,17.78 130.844,18.55 U2_E.4@131.808,18.55 132.834,18.55 133.35,18.034 v1(133.35,16.764)
  Bottom Layer w0.381: v1(133.35,16.764) 135.049,18.463 135.049,30.94 v1(133.858,32.131)
NetC17_F_1: C17_F.1 D4_F.1 R6_F.1 U2_F.4 | length 22.4
  Top Layer w0.254: C17_F.1@156.883,17.78 157.633,17.78 158.403,18.55 U2_F.4@159.367,18.55 160.393,18.55 160.909,18.034 v1(160.909,16.764)
  Bottom Layer w0.381: v1(160.909,16.764) 162.608,18.463 162.608,30.94 v1(161.417,32.131)
NetC17_G_1: C17_G.1 D4_G.1 R6_G.1 U2_G.4 | length 22.4
  Top Layer w0.254: C17_G.1@184.442,17.78 185.192,17.78 185.962,18.55 U2_G.4@186.926,18.55 187.952,18.55 188.468,18.034 v1(188.468,16.764)
  Bottom Layer w0.381: v1(188.468,16.764) 190.167,18.463 190.167,30.94 v1(188.976,32.131)
NetC17_H_1: C17_H.1 D4_H.1 R6_H.1 U2_H.4 | length 22.4
  Top Layer w0.254: C17_H.1@212.001,17.78 212.751,17.78 213.521,18.55 U2_H.4@214.485,18.55 215.511,18.55 216.027,18.034 v1(216.027,16.764)
  Bottom Layer w0.381: v1(216.027,16.764) 217.726,18.463 217.726,30.94 v1(216.535,32.131)
NetC18_A_1: C18_A.1 R15_A.1 U2_A.8 | length 6.6
  Top Layer w0.254: R15_A.1@23.622,22.314 23.622,19.812 24.384,19.05 U2_A.8@25.672,19.05
  Top Layer w0.381: R15_A.1@23.622,22.314 C18_A.1@25.4,22.314
NetC18_B_1: C18_B.1 R15_B.1 U2_B.8 | length 6.6
  Top Layer w0.254: R15_B.1@51.181,22.314 51.181,19.812 51.943,19.05 U2_B.8@53.231,19.05
  Top Layer w0.381: R15_B.1@51.181,22.314 C18_B.1@52.959,22.314
NetC18_C_1: C18_C.1 R15_C.1 U2_C.8 | length 6.6
  Top Layer w0.254: R15_C.1@78.74,22.314 78.74,19.812 79.502,19.05 U2_C.8@80.79,19.05
  Top Layer w0.381: R15_C.1@78.74,22.314 C18_C.1@80.518,22.314
NetC18_D_1: C18_D.1 R15_D.1 U2_D.8 | length 6.6
  Top Layer w0.254: R15_D.1@106.299,22.314 106.299,19.812 107.061,19.05 U2_D.8@108.349,19.05
  Top Layer w0.381: R15_D.1@106.299,22.314 C18_D.1@108.077,22.314
NetC18_E_1: C18_E.1 R15_E.1 U2_E.8 | length 6.6
  Top Layer w0.254: R15_E.1@133.858,22.314 133.858,19.812 134.62,19.05 U2_E.8@135.908,19.05
  Top Layer w0.381: R15_E.1@133.858,22.314 C18_E.1@135.636,22.314
NetC18_F_1: C18_F.1 R15_F.1 U2_F.8 | length 6.6
  Top Layer w0.254: R15_F.1@161.417,22.314 161.417,19.812 162.179,19.05 U2_F.8@163.467,19.05
  Top Layer w0.381: R15_F.1@161.417,22.314 C18_F.1@163.195,22.314
NetC18_G_1: C18_G.1 R15_G.1 U2_G.8 | length 6.6
  Top Layer w0.254: R15_G.1@188.976,22.314 188.976,19.812 189.738,19.05 U2_G.8@191.026,19.05
  Top Layer w0.381: R15_G.1@188.976,22.314 C18_G.1@190.754,22.314
NetC18_H_1: C18_H.1 R15_H.1 U2_H.8 | length 6.6
  Top Layer w0.254: R15_H.1@216.535,22.314 216.535,19.812 217.297,19.05 U2_H.8@218.585,19.05
  Top Layer w0.381: R15_H.1@216.535,22.314 C18_H.1@218.313,22.314
NetC19_A_1: C19_A.1 C20_A.1 C21_A.1 R17_A.1 | length 10.8
  Top Layer w0.381: R17_A.1@26.67,75.984 26.759,76.073 27.686,76.073 v1(28.194,75.565) 28.713,76.084 C21_A.1@29.718,76.084 ; C21_A.1@29.529,76.073 C21_A.1@29.618,75.984
  Bottom Layer w0.381: C19_A.1@22.098,74.348 C20_A.1@25.654,74.348 25.654,75.248 25.971,75.565 v1(28.194,75.565)
NetC19_B_1: C19_B.1 C20_B.1 C21_B.1 R17_B.1 | length 10.8
  Top Layer w0.381: R17_B.1@54.229,75.984 54.318,76.073 55.245,76.073 v1(55.753,75.565) 56.272,76.084 C21_B.1@57.277,76.084 ; C21_B.1@57.088,76.073 C21_B.1@57.177,75.984
  Bottom Layer w0.381: C19_B.1@49.657,74.348 C20_B.1@53.213,74.348 53.213,75.248 53.53,75.565 v1(55.753,75.565)
NetC19_C_1: C19_C.1 C20_C.1 C21_C.1 R17_C.1 | length 10.8
  Top Layer w0.381: R17_C.1@81.788,75.984 81.877,76.073 82.804,76.073 v1(83.312,75.565) 83.831,76.084 C21_C.1@84.836,76.084 ; C21_C.1@84.647,76.073 C21_C.1@84.736,75.984
  Bottom Layer w0.381: C19_C.1@77.216,74.348 C20_C.1@80.772,74.348 80.772,75.248 81.089,75.565 v1(83.312,75.565)
NetC19_D_1: C19_D.1 C20_D.1 C21_D.1 R17_D.1 | length 10.8
  Top Layer w0.381: R17_D.1@109.347,75.984 109.436,76.073 110.363,76.073 v1(110.871,75.565) 111.39,76.084 C21_D.1@112.395,76.084 ; C21_D.1@112.206,76.073 C21_D.1@112.295,75.984
  Bottom Layer w0.381: C19_D.1@104.775,74.348 C20_D.1@108.331,74.348 108.331,75.248 108.648,75.565 v1(110.871,75.565)
NetC19_E_1: C19_E.1 C20_E.1 C21_E.1 R17_E.1 | length 10.8
  Top Layer w0.381: R17_E.1@136.906,75.984 136.995,76.073 137.922,76.073 v1(138.43,75.565) 138.949,76.084 C21_E.1@139.954,76.084 ; C21_E.1@139.765,76.073 C21_E.1@139.854,75.984
  Bottom Layer w0.381: C19_E.1@132.334,74.348 C20_E.1@135.89,74.348 135.89,75.248 136.207,75.565 v1(138.43,75.565)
